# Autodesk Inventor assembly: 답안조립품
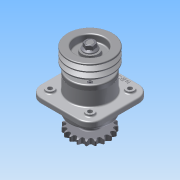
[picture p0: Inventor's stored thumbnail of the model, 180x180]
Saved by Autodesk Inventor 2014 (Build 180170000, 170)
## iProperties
Created: 2015-09
Part Number: 답안조립품
Document SubType Name: Assembly
Designer: study
Author: study
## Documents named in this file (12)
- C:\Users\study\Desktop\450909V1011\답안조립품.iam
- C:\Users\study\Desktop\450909V1011\1-본체.ipt
- C:\Users\study\Desktop\450909V1011\2-커버.ipt
- C:\Users\study\Desktop\450909V1011\3-축.ipt
- C:\Users\study\Desktop\450909V1011\6-베어링 6206.ipt
- C:\Users\study\Desktop\450909V1011\11-키 6x6.ipt
- C:\Users\study\Desktop\450909V1011\8-오일실 30x42.ipt
- C:\Users\study\Desktop\450909V1011\7-부시.ipt
- C:\Users\study\Desktop\450909V1011\10-M6.ipt
- C:\Users\study\Desktop\450909V1011\4-V벨트풀리.ipt
- C:\Users\study\Desktop\450909V1011\9-M16-너트.ipt
- C:\Users\study\Desktop\450909V1011\5-체인 스프로킷.ipt
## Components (23 placed, 11 different names)
1. 1-본체:1
2. 2-커버:1
3. 2-커버:2
4. 3-축:1 — 각도:1, 각도:2
5. 6-베어링 6206:1
6. 6-베어링 6206:2
7. 11-키 6x6:1 — 각도:1, 각도:3
8. 11-키 6x6:2 — 각도:2, 각도:4
9. 8-8-오일실 30x42:1
10. 8-8-오일실 30x42:2
11. 7-부시:1
12. 4-V벨트풀리:1 — 각도:3
13. 9-M16 너트:1
14. 5-체인 스프로킷:1 — 각도:4, 각도:5
15. 9-M16 너트:2 — 각도:5
16. 10-M6:1
17. 10-M6:2
18. 10-M6:3
19. 10-M6:4
20. 10-M6:5
21. 10-M6:6
22. 10-M6:7
23. 10-M6:8
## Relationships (5: Angle 5)
- 각도:1 [Angle]: 3-축:1 ↔ 11-키 6x6:1
- 각도:2 [Angle]: 3-축:1 ↔ 11-키 6x6:2
- 각도:3 [Angle]: 11-키 6x6:1 ↔ 4-V벨트풀리:1
- 각도:4 [Angle]: 11-키 6x6:2 ↔ 5-체인 스프로킷:1
- 각도:5 [Angle]: 5-체인 스프로킷:1 ↔ 9-M16 너트:2
